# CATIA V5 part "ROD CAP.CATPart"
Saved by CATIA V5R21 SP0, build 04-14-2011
Part number: Part1.2.3
Bounding box of the stored display mesh (mm): x -13 to 13, y 0 to 36, z -42 to 42
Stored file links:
  G:\CATIA\PROJECT__01\ROD CAP.CATPart
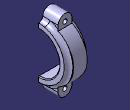
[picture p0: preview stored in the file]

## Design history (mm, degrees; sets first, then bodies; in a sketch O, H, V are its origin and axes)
Body1 (main body)
  Sketch1 on yz-plane, origin (0, 0, 0), H (0, 1, 0), V (0, 0, 1)
    arc A1 centre (0, 0) radius 30 from (0, -30) to (0, 30) ccw
    arc A2 centre (0, 0) radius 24 from (0, -24) to (0, 24) ccw
    line L1 (0, 30) -> (0, 24)
    point P1 (0, 30)
    point P4 (0, -24)
    line L2 (0, -24) -> (0, -30)
    radius A1 = 30
    radius A2 = 24
    coincidence: P1 V, L1 P4, L1 L2
    vertical: L1 V, L2 V
  Pad1: profile Sketch1, direction (1, 0, 0), length 13, mirrored extent
  Sketch2 on yz-plane, origin (0, 0, 0), H (0, 1, 0), V (0, 0, 1)
    projected arc E1 centre (0, 0) radius 30 from (0, -30) to (0, 30) ccw from edge [face of Pad1 from Sketch1.A1 | end face of Pad1]
    point P1 (0, -30)
    point P2 (0, 30)
    line L1 (0, 30) -> (0, 42)
    point P3 (0, 42)
    line L2 (0, 42) -> (18, 42)
    point P4 (18, 42)
    line L3 (18, 42) -> (18, 28.1425)
    arc A1 centre (5, 0) radius 31 from (18, -28.1425) to (18, 28.1425) ccw
    point P5 (5, 0)
    point P6 (0, -30)
    point P7 (0, -42)
    point P8 (18, -42)
    line L4 (0, -30) -> (0, -42)
    line L5 (0, -42) -> (18, -42)
    line L6 (18, -42) -> (18, -28.1425)
    length L1 = 12
    length L2 = 18
    radius A1 = 31
    distance P5 O = 5
    vertical: L1 V, L3 V
    horizontal: L2 H
    coincidence: P5 H, P1 P6
    symmetry: P2 P6 H, P3 P7 H, P4 P8 H, L1 L4 H, L2 L5 H, L3 L6 H
  Pad2: profile Sketch2, direction (1, 0, 0), length 8, mirrored extent
  TritangentFillet1: Face1 start face of Pad2, Face2 end face of Pad2, RemoveFace face of Pad2 from Sketch2.L5
  TritangentFillet2: Face1 end face of Pad2, Face2 start face of Pad2, RemoveFace face of Pad2 from Sketch2.L2
  Fillet1: radius 5, on edge [start face of Pad2 | face of Pad1 from Sketch1.A1]; edge [face of Pad1 from Sketch1.A1 | end face of Pad2]
  Chamfer1: length 1, angle 45, on edge [start face of Pad1 | face of Pad1 from Sketch1.A2]; edge [face of Pad1 from Sketch1.A2 | end face of Pad1]
  Sketch3 on face of Pad2 from Sketch2.L3, origin (0, 18, 0), H (-1, 0, 0), V (0, 0, 1)
    circle A1 centre (0, 34) radius 2.5
    reference projected arc E1 centre (0, 34) radius 8 from (8, 34) to (-8, 34) ccw from edge [face of Pad2 from Sketch2.L3 | face of TritangentFillet2]
    reference projected line E2 through (0, 0) direction (-1, 0) from axis of face of Pad2 from Sketch2.A1
    circle A2 centre (0, -34) radius 2.5
    radius A1 = 2.5
    concentricity: A1 E1
    symmetry: A1 A2 E2
  Pocket1: profile Sketch3, direction (0, -1, 0), through (limit type 3)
